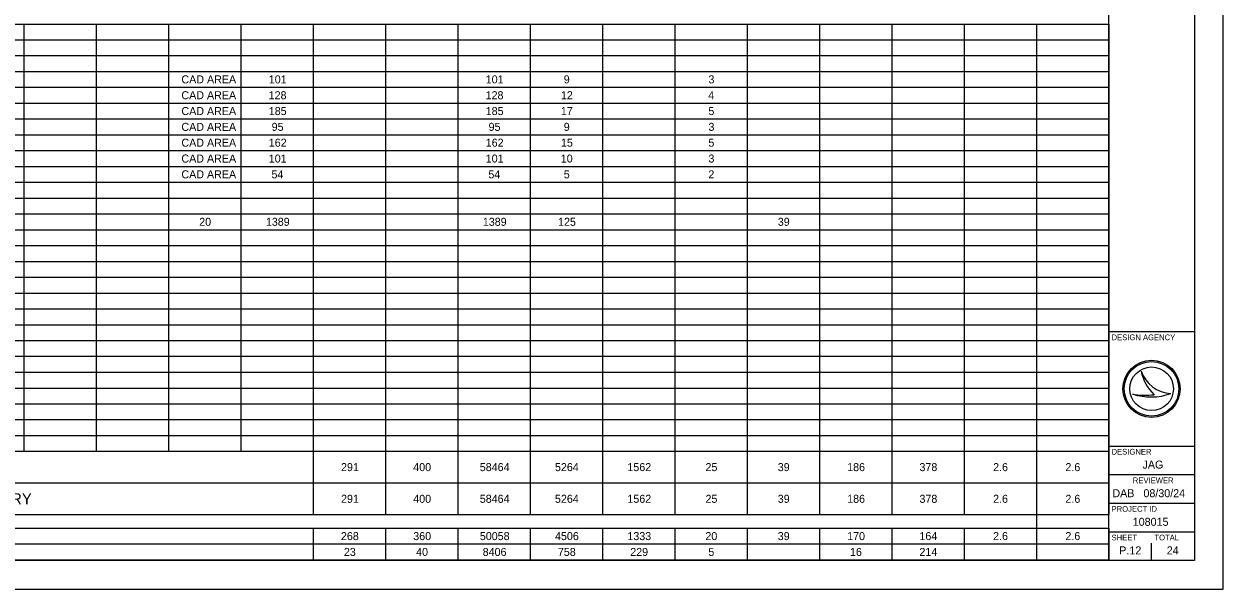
# Model space of a CAD drawing. Extents: x 0 to 34, y 0 to 22.
# Drawn here: x 13.03 to 34, y 0 to 9.88 of the extents above; entities that cross this region are included whole.
import ezdxf

# ---------------------------------------------------------------- set-up
doc = ezdxf.new("R2010")
doc.units = 0
for name, color, linetype in [('SH_Border', 7, 'Continuous'), ('SH_Cut_Line', 7, 'Continuous'), ('SH_Data', 7, 'Continuous'), ('SH_Text', 7, 'Continuous')]:
    doc.layers.add(name, color=color, linetype=linetype)

msp = doc.modelspace()

# ---------------------------------------------------------------- linework, layer by layer
at = {"layer": 'SH_Border'}
for p, q in [((32, 0.5), (32, 21.5)), ((32, 4.5), (33.5, 4.5)), ((32, 2.5), (33.5, 2.5)), ((32, 2), (33.5, 2)), ((32, 1.5), (33.5, 1.5)), ((32, 1), (33.5, 1))]:
    msp.add_line(p, q, dxfattribs=at)
msp.add_lwpolyline([(1.5, 21.5), (33.5, 21.5), (33.5, 0.5), (1.5, 0.5)], close=True, dxfattribs=at)
at = {"layer": 'SH_Cut_Line'}
msp.add_lwpolyline([(0, 0), (34, 0), (34, 22), (0, 22)], close=True, dxfattribs=at)
at = {"layer": 'SH_Data'}
for p, q in [((32.567, 3.81), (32.567, 3.81)), ((32.417, 3.41), (32.417, 3.41)), ((32.75, 3.5), (32.75, 3.5)), ((33.087, 3.419), (33.087, 3.419)), ((32.375, 0.675), (32.375, 0.675)), ((32.75, 0.5), (32.75, 0.8))]:
    msp.add_line(p, q, dxfattribs=at)
for radius in [0.5, 0.477, 0.477, 0.382]:
    msp.add_circle((32.75, 3.5), radius, dxfattribs=at)
for centre, radius, start, end in [((33.116, 3.998), 0.58, 198.9257, 198.9319), ((33.347, 3.97), 0.796, 191.6379, 191.6421), ((33.116, 3.998), 0.58, 198.9319, 267.1657), ((33.347, 3.97), 0.796, 191.6421, 226.0947), ((32.739, 4.37), 1.013, 251.4576, 290.0832), ((32.648, 4.654), 1.266, 259.4964, 259.4995), ((32.739, 4.37), 1.013, 251.4527, 251.4576), ((32.648, 4.654), 1.266, 259.4995, 276.6672)]:
    msp.add_arc(centre, radius, start, end, dxfattribs=at)
at = {"layer": 'SH_Text'}
for p, q in [((8.427, 9.878), (13.026, 9.878)), ((13.026, 9.878), (15.556, 9.878)), ((13.026, 9.878), (13.026, 9.325)), ((14.291, 9.878), (14.291, 9.325)), ((15.556, 9.878), (23.145, 9.878)), ((15.556, 9.878), (15.556, 9.325)), ((16.821, 9.878), (16.821, 9.325)), ((18.086, 9.878), (18.086, 9.325)), ((19.351, 9.878), (19.351, 9.325)), ((20.616, 9.878), (20.616, 9.325)), ((21.88, 9.878), (21.88, 9.325)), ((23.145, 9.878), (24.41, 9.878)), ((23.145, 9.878), (23.145, 9.325)), ((24.41, 9.878), (25.675, 9.878)), ((24.41, 9.878), (24.41, 9.325)), ((25.675, 9.878), (26.94, 9.878)), ((25.675, 9.878), (25.675, 9.325)), ((26.94, 9.878), (28.205, 9.878)), ((26.94, 9.878), (26.94, 9.325)), ((28.205, 9.878), (29.47, 9.878)), ((28.205, 9.878), (28.205, 9.325)), ((29.47, 9.878), (30.735, 9.878)), ((29.47, 9.878), (29.47, 9.325)), ((30.735, 9.878), (32, 9.878)), ((30.735, 9.878), (30.735, 9.325)), ((32, 9.878), (32, 9.325)), ((8.427, 9.602), (13.026, 9.602)), ((13.026, 9.602), (15.556, 9.602)), ((15.556, 9.602), (23.145, 9.602)), ((23.145, 9.602), (24.41, 9.602)), ((24.41, 9.602), (25.675, 9.602)), ((25.675, 9.602), (26.94, 9.602)), ((26.94, 9.602), (28.205, 9.602)), ((28.205, 9.602), (29.47, 9.602)), ((29.47, 9.602), (30.735, 9.602)), ((30.735, 9.602), (32, 9.602)), ((8.427, 9.325), (13.026, 9.325)), ((13.026, 9.325), (15.556, 9.325)), ((13.026, 9.325), (13.026, 8.495)), ((14.291, 9.325), (14.291, 8.495)), ((15.556, 9.325), (23.145, 9.325)), ((15.556, 9.325), (15.556, 8.495)), ((16.821, 9.325), (16.821, 8.495)), ((18.086, 9.325), (18.086, 8.495)), ((19.351, 9.325), (19.351, 8.495)), ((20.616, 9.325), (20.616, 8.495)), ((21.88, 9.325), (21.88, 8.495)), ((23.145, 9.325), (24.41, 9.325)), ((23.145, 9.325), (23.145, 8.495)), ((24.41, 9.325), (25.675, 9.325)), ((24.41, 9.325), (24.41, 8.495)), ((25.675, 9.325), (26.94, 9.325)), ((25.675, 9.325), (25.675, 8.495)), ((26.94, 9.325), (28.205, 9.325)), ((26.94, 9.325), (26.94, 8.495)), ((28.205, 9.325), (29.47, 9.325)), ((28.205, 9.325), (28.205, 8.495)), ((29.47, 9.325), (30.735, 9.325)), ((29.47, 9.325), (29.47, 8.495)), ((30.735, 9.325), (32, 9.325)), ((30.735, 9.325), (30.735, 8.495)), ((32, 9.325), (32, 8.495)), ((8.427, 9.048), (13.026, 9.048)), ((13.026, 9.048), (15.556, 9.048)), ((15.556, 9.048), (23.145, 9.048)), ((23.145, 9.048), (24.41, 9.048)), ((24.41, 9.048), (25.675, 9.048)), ((25.675, 9.048), (26.94, 9.048)), ((26.94, 9.048), (28.205, 9.048)), ((28.205, 9.048), (29.47, 9.048)), ((29.47, 9.048), (30.735, 9.048)), ((30.735, 9.048), (32, 9.048)), ((8.427, 8.772), (13.026, 8.772)), ((13.026, 8.772), (15.556, 8.772)), ((15.556, 8.772), (23.145, 8.772)), ((23.145, 8.772), (24.41, 8.772)), ((24.41, 8.772), (25.675, 8.772)), ((25.675, 8.772), (26.94, 8.772)), ((26.94, 8.772), (28.205, 8.772)), ((28.205, 8.772), (29.47, 8.772)), ((29.47, 8.772), (30.735, 8.772)), ((30.735, 8.772), (32, 8.772)), ((8.427, 8.495), (13.026, 8.495)), ((13.026, 8.495), (15.556, 8.495)), ((13.026, 8.495), (13.026, 7.941)), ((14.291, 8.495), (14.291, 7.941)), ((15.556, 8.495), (23.145, 8.495)), ((15.556, 8.495), (15.556, 7.941)), ((16.821, 8.495), (16.821, 7.941)), ((18.086, 8.495), (18.086, 7.941)), ((19.351, 8.495), (19.351, 7.941)), ((20.616, 8.495), (20.616, 7.941)), ((21.88, 8.495), (21.88, 7.941)), ((23.145, 8.495), (24.41, 8.495)), ((23.145, 8.495), (23.145, 7.941)), ((24.41, 8.495), (25.675, 8.495)), ((24.41, 8.495), (24.41, 7.941)), ((25.675, 8.495), (26.94, 8.495)), ((25.675, 8.495), (25.675, 7.941)), ((26.94, 8.495), (28.205, 8.495)), ((26.94, 8.495), (26.94, 7.941)), ((28.205, 8.495), (29.47, 8.495)), ((28.205, 8.495), (28.205, 7.941)), ((29.47, 8.495), (30.735, 8.495)), ((29.47, 8.495), (29.47, 7.941)), ((30.735, 8.495), (32, 8.495)), ((30.735, 8.495), (30.735, 7.941)), ((32, 8.495), (32, 7.941)), ((8.427, 8.218), (13.026, 8.218)), ((13.026, 8.218), (15.556, 8.218)), ((15.556, 8.218), (23.145, 8.218)), ((23.145, 8.218), (24.41, 8.218)), ((24.41, 8.218), (25.675, 8.218)), ((25.675, 8.218), (26.94, 8.218)), ((26.94, 8.218), (28.205, 8.218)), ((28.205, 8.218), (29.47, 8.218)), ((29.47, 8.218), (30.735, 8.218)), ((30.735, 8.218), (32, 8.218)), ((8.427, 7.941), (13.026, 7.941)), ((13.026, 7.941), (15.556, 7.941)), ((13.026, 7.941), (13.026, 7.111)), ((14.291, 7.941), (14.291, 7.111)), ((15.556, 7.941), (23.145, 7.941)), ((15.556, 7.941), (15.556, 7.111)), ((16.821, 7.941), (16.821, 7.111)), ((18.086, 7.941), (18.086, 7.111)), ((19.351, 7.941), (19.351, 7.111)), ((20.616, 7.941), (20.616, 7.111)), ((21.88, 7.941), (21.88, 7.111)), ((23.145, 7.941), (24.41, 7.941)), ((23.145, 7.941), (23.145, 7.111)), ((24.41, 7.941), (25.675, 7.941)), ((24.41, 7.941), (24.41, 7.111)), ((25.675, 7.941), (26.94, 7.941)), ((25.675, 7.941), (25.675, 7.111)), ((26.94, 7.941), (28.205, 7.941)), ((26.94, 7.941), (26.94, 7.111)), ((28.205, 7.941), (29.47, 7.941)), ((28.205, 7.941), (28.205, 7.111)), ((29.47, 7.941), (30.735, 7.941)), ((29.47, 7.941), (29.47, 7.111)), ((30.735, 7.941), (32, 7.941)), ((30.735, 7.941), (30.735, 7.111)), ((32, 7.941), (32, 7.111)), ((8.427, 7.665), (13.026, 7.665)), ((13.026, 7.665), (15.556, 7.665)), ((15.556, 7.665), (23.145, 7.665)), ((23.145, 7.665), (24.41, 7.665)), ((24.41, 7.665), (25.675, 7.665)), ((25.675, 7.665), (26.94, 7.665)), ((26.94, 7.665), (28.205, 7.665)), ((28.205, 7.665), (29.47, 7.665)), ((29.47, 7.665), (30.735, 7.665)), ((30.735, 7.665), (32, 7.665)), ((8.427, 7.388), (13.026, 7.388)), ((13.026, 7.388), (15.556, 7.388)), ((15.556, 7.388), (23.145, 7.388)), ((23.145, 7.388), (24.41, 7.388)), ((24.41, 7.388), (25.675, 7.388)), ((25.675, 7.388), (26.94, 7.388)), ((26.94, 7.388), (28.205, 7.388)), ((28.205, 7.388), (29.47, 7.388)), ((29.47, 7.388), (30.735, 7.388)), ((30.735, 7.388), (32, 7.388)), ((8.427, 7.111), (13.026, 7.111)), ((13.026, 7.111), (15.556, 7.111)), ((13.026, 7.111), (13.026, 6.558)), ((14.291, 7.111), (14.291, 6.558)), ((15.556, 7.111), (23.145, 7.111)), ((15.556, 7.111), (15.556, 6.558)), ((16.821, 7.111), (16.821, 6.558)), ((18.086, 7.111), (18.086, 6.558)), ((19.351, 7.111), (19.351, 6.558)), ((20.616, 7.111), (20.616, 6.558)), ((21.88, 7.111), (21.88, 6.558)), ((23.145, 7.111), (24.41, 7.111)), ((23.145, 7.111), (23.145, 6.558)), ((24.41, 7.111), (25.675, 7.111)), ((24.41, 7.111), (24.41, 6.558)), ((25.675, 7.111), (26.94, 7.111)), ((25.675, 7.111), (25.675, 6.558)), ((26.94, 7.111), (28.205, 7.111)), ((26.94, 7.111), (26.94, 6.558)), ((28.205, 7.111), (29.47, 7.111)), ((28.205, 7.111), (28.205, 6.558)), ((29.47, 7.111), (30.735, 7.111)), ((29.47, 7.111), (29.47, 6.558)), ((30.735, 7.111), (32, 7.111)), ((30.735, 7.111), (30.735, 6.558)), ((32, 7.111), (32, 6.558)), ((8.427, 6.835), (13.026, 6.835)), ((13.026, 6.835), (15.556, 6.835)), ((15.556, 6.835), (23.145, 6.835)), ((23.145, 6.835), (24.41, 6.835)), ((24.41, 6.835), (25.675, 6.835)), ((25.675, 6.835), (26.94, 6.835)), ((26.94, 6.835), (28.205, 6.835)), ((28.205, 6.835), (29.47, 6.835)), ((29.47, 6.835), (30.735, 6.835)), ((30.735, 6.835), (32, 6.835)), ((8.427, 6.558), (13.026, 6.558)), ((13.026, 6.558), (15.556, 6.558)), ((13.026, 6.558), (13.026, 2.407)), ((14.291, 6.558), (14.291, 2.407)), ((15.556, 6.558), (23.145, 6.558)), ((15.556, 6.558), (15.556, 2.407)), ((16.821, 6.558), (16.821, 2.407)), ((18.086, 6.558), (18.086, 1.3)), ((19.351, 6.558), (19.351, 1.3)), ((20.616, 6.558), (20.616, 1.3)), ((21.88, 6.558), (21.88, 1.3)), ((23.145, 6.558), (24.41, 6.558)), ((23.145, 6.558), (23.145, 1.3)), ((24.41, 6.558), (25.675, 6.558)), ((24.41, 6.558), (24.41, 1.3)), ((25.675, 6.558), (26.94, 6.558)), ((25.675, 6.558), (25.675, 1.3)), ((26.94, 6.558), (28.205, 6.558)), ((26.94, 6.558), (26.94, 1.3)), ((28.205, 6.558), (29.47, 6.558)), ((28.205, 6.558), (28.205, 1.3)), ((29.47, 6.558), (30.735, 6.558)), ((29.47, 6.558), (29.47, 1.3)), ((30.735, 6.558), (32, 6.558)), ((30.735, 6.558), (30.735, 0.51)), ((32, 6.558), (32, 1.3)), ((8.427, 6.281), (13.026, 6.281)), ((13.026, 6.281), (15.556, 6.281)), ((15.556, 6.281), (23.145, 6.281)), ((23.145, 6.281), (24.41, 6.281)), ((24.41, 6.281), (25.675, 6.281)), ((25.675, 6.281), (26.94, 6.281)), ((26.94, 6.281), (28.205, 6.281)), ((28.205, 6.281), (29.47, 6.281)), ((29.47, 6.281), (30.735, 6.281)), ((30.735, 6.281), (32, 6.281)), ((8.427, 6.004), (13.026, 6.004)), ((13.026, 6.004), (15.556, 6.004)), ((15.556, 6.004), (23.145, 6.004)), ((23.145, 6.004), (24.41, 6.004)), ((24.41, 6.004), (25.675, 6.004)), ((25.675, 6.004), (26.94, 6.004)), ((26.94, 6.004), (28.205, 6.004)), ((28.205, 6.004), (29.47, 6.004)), ((29.47, 6.004), (30.735, 6.004)), ((30.735, 6.004), (32, 6.004)), ((8.427, 5.728), (13.026, 5.728)), ((13.026, 5.728), (15.556, 5.728)), ((15.556, 5.728), (23.145, 5.728)), ((23.145, 5.728), (24.41, 5.728)), ((24.41, 5.728), (25.675, 5.728)), ((25.675, 5.728), (26.94, 5.728)), ((26.94, 5.728), (28.205, 5.728)), ((28.205, 5.728), (29.47, 5.728)), ((29.47, 5.728), (30.735, 5.728)), ((30.735, 5.728), (32, 5.728)), ((8.427, 5.451), (13.026, 5.451)), ((13.026, 5.451), (15.556, 5.451)), ((15.556, 5.451), (23.145, 5.451)), ((23.145, 5.451), (24.41, 5.451)), ((24.41, 5.451), (25.675, 5.451)), ((25.675, 5.451), (26.94, 5.451)), ((26.94, 5.451), (28.205, 5.451)), ((28.205, 5.451), (29.47, 5.451)), ((29.47, 5.451), (30.735, 5.451)), ((30.735, 5.451), (32, 5.451)), ((8.427, 5.174), (13.026, 5.174)), ((13.026, 5.174), (15.556, 5.174)), ((15.556, 5.174), (23.145, 5.174)), ((23.145, 5.174), (24.41, 5.174)), ((24.41, 5.174), (25.675, 5.174)), ((25.675, 5.174), (26.94, 5.174)), ((26.94, 5.174), (28.205, 5.174)), ((28.205, 5.174), (29.47, 5.174)), ((29.47, 5.174), (30.735, 5.174)), ((30.735, 5.174), (32, 5.174)), ((8.427, 4.898), (13.026, 4.898)), ((13.026, 4.898), (15.556, 4.898)), ((15.556, 4.898), (23.145, 4.898)), ((23.145, 4.898), (24.41, 4.898)), ((24.41, 4.898), (25.675, 4.898)), ((25.675, 4.898), (26.94, 4.898)), ((26.94, 4.898), (28.205, 4.898)), ((28.205, 4.898), (29.47, 4.898)), ((29.47, 4.898), (30.735, 4.898)), ((30.735, 4.898), (32, 4.898)), ((8.427, 4.621), (13.026, 4.621)), ((13.026, 4.621), (15.556, 4.621)), ((15.556, 4.621), (23.145, 4.621)), ((23.145, 4.621), (24.41, 4.621)), ((24.41, 4.621), (25.675, 4.621)), ((25.675, 4.621), (26.94, 4.621)), ((26.94, 4.621), (28.205, 4.621)), ((28.205, 4.621), (29.47, 4.621)), ((29.47, 4.621), (30.735, 4.621)), ((30.735, 4.621), (32, 4.621)), ((8.427, 4.344), (13.026, 4.344)), ((13.026, 4.344), (15.556, 4.344)), ((15.556, 4.344), (23.145, 4.344)), ((23.145, 4.344), (24.41, 4.344)), ((24.41, 4.344), (25.675, 4.344)), ((25.675, 4.344), (26.94, 4.344)), ((26.94, 4.344), (28.205, 4.344)), ((28.205, 4.344), (29.47, 4.344)), ((29.47, 4.344), (30.735, 4.344)), ((30.735, 4.344), (32, 4.344)), ((8.427, 4.068), (13.026, 4.068)), ((13.026, 4.068), (15.556, 4.068)), ((15.556, 4.068), (23.145, 4.068)), ((23.145, 4.068), (24.41, 4.068)), ((24.41, 4.068), (25.675, 4.068)), ((25.675, 4.068), (26.94, 4.068)), ((26.94, 4.068), (28.205, 4.068)), ((28.205, 4.068), (29.47, 4.068)), ((29.47, 4.068), (30.735, 4.068)), ((30.735, 4.068), (32, 4.068)), ((8.427, 3.791), (13.026, 3.791)), ((13.026, 3.791), (15.556, 3.791)), ((15.556, 3.791), (23.145, 3.791)), ((23.145, 3.791), (24.41, 3.791)), ((24.41, 3.791), (25.675, 3.791)), ((25.675, 3.791), (26.94, 3.791)), ((26.94, 3.791), (28.205, 3.791)), ((28.205, 3.791), (29.47, 3.791)), ((29.47, 3.791), (30.735, 3.791)), ((30.735, 3.791), (32, 3.791)), ((8.427, 3.514), (13.026, 3.514)), ((13.026, 3.514), (15.556, 3.514)), ((15.556, 3.514), (23.145, 3.514)), ((23.145, 3.514), (24.41, 3.514)), ((24.41, 3.514), (25.675, 3.514)), ((25.675, 3.514), (26.94, 3.514)), ((26.94, 3.514), (28.205, 3.514)), ((28.205, 3.514), (29.47, 3.514)), ((29.47, 3.514), (30.735, 3.514)), ((30.735, 3.514), (32, 3.514)), ((8.427, 3.237), (13.026, 3.237)), ((13.026, 3.237), (15.556, 3.237)), ((15.556, 3.237), (23.145, 3.237)), ((23.145, 3.237), (24.41, 3.237)), ((24.41, 3.237), (25.675, 3.237)), ((25.675, 3.237), (26.94, 3.237)), ((26.94, 3.237), (28.205, 3.237)), ((28.205, 3.237), (29.47, 3.237)), ((29.47, 3.237), (30.735, 3.237)), ((30.735, 3.237), (32, 3.237)), ((8.427, 2.961), (13.026, 2.961)), ((13.026, 2.961), (15.556, 2.961)), ((15.556, 2.961), (23.145, 2.961)), ((23.145, 2.961), (24.41, 2.961)), ((24.41, 2.961), (25.675, 2.961)), ((25.675, 2.961), (26.94, 2.961)), ((26.94, 2.961), (28.205, 2.961)), ((28.205, 2.961), (29.47, 2.961)), ((29.47, 2.961), (30.735, 2.961)), ((30.735, 2.961), (32, 2.961)), ((8.427, 2.684), (13.026, 2.684)), ((13.026, 2.684), (15.556, 2.684)), ((15.556, 2.684), (23.145, 2.684)), ((23.145, 2.684), (24.41, 2.684)), ((24.41, 2.684), (25.675, 2.684)), ((25.675, 2.684), (26.94, 2.684)), ((26.94, 2.684), (28.205, 2.684)), ((28.205, 2.684), (29.47, 2.684)), ((29.47, 2.684), (30.735, 2.684)), ((30.735, 2.684), (32, 2.684)), ((8.427, 2.407), (13.026, 2.407)), ((13.026, 2.407), (15.556, 2.407)), ((15.556, 2.407), (23.145, 2.407)), ((23.145, 2.407), (24.41, 2.407)), ((24.41, 2.407), (25.675, 2.407)), ((25.675, 2.407), (26.94, 2.407)), ((26.94, 2.407), (28.205, 2.407)), ((28.205, 2.407), (29.47, 2.407)), ((29.47, 2.407), (30.735, 2.407)), ((30.735, 2.407), (32, 2.407)), ((8.427, 1.854), (13.026, 1.854)), ((13.026, 1.854), (15.556, 1.854)), ((15.556, 1.854), (23.145, 1.854)), ((23.145, 1.854), (24.41, 1.854)), ((24.41, 1.854), (25.675, 1.854)), ((25.675, 1.854), (26.94, 1.854)), ((26.94, 1.854), (28.205, 1.854)), ((28.205, 1.854), (29.47, 1.854)), ((29.47, 1.854), (30.735, 1.854)), ((30.735, 1.854), (32, 1.854)), ((8.427, 1.3), (13.026, 1.3)), ((13.026, 1.3), (15.556, 1.3)), ((15.556, 1.3), (23.145, 1.3)), ((23.145, 1.3), (24.41, 1.3)), ((24.41, 1.3), (25.675, 1.3)), ((25.675, 1.3), (26.94, 1.3)), ((26.94, 1.3), (28.205, 1.3)), ((28.205, 1.3), (29.47, 1.3)), ((29.47, 1.3), (30.735, 1.3)), ((30.735, 1.3), (32, 1.3)), ((8.427, 1.063), (13.026, 1.063)), ((13.026, 1.063), (15.556, 1.063)), ((15.556, 1.063), (23.145, 1.063)), ((18.086, 1.063), (18.086, 0.51)), ((19.351, 1.063), (19.351, 0.51)), ((20.616, 1.063), (20.616, 0.51)), ((21.88, 1.063), (21.88, 0.51)), ((23.145, 1.063), (24.41, 1.063)), ((23.145, 1.063), (23.145, 0.51)), ((24.41, 1.063), (25.675, 1.063)), ((24.41, 1.063), (24.41, 0.51)), ((25.675, 1.063), (26.94, 1.063)), ((25.675, 1.063), (25.675, 0.51)), ((26.94, 1.063), (28.205, 1.063)), ((26.94, 1.063), (26.94, 0.51)), ((28.205, 1.063), (29.47, 1.063)), ((28.205, 1.063), (28.205, 0.51)), ((29.47, 1.063), (30.735, 1.063)), ((29.47, 1.063), (29.47, 0.51)), ((30.735, 1.063), (32, 1.063)), ((32, 1.063), (32, 0.51)), ((8.427, 0.787), (13.026, 0.787)), ((13.026, 0.787), (15.556, 0.787)), ((15.556, 0.787), (23.145, 0.787)), ((23.145, 0.787), (24.41, 0.787)), ((24.41, 0.787), (25.675, 0.787)), ((25.675, 0.787), (26.94, 0.787)), ((26.94, 0.787), (28.205, 0.787)), ((28.205, 0.787), (29.47, 0.787)), ((29.47, 0.787), (30.735, 0.787)), ((30.735, 0.787), (32, 0.787)), ((8.427, 0.51), (13.026, 0.51)), ((13.026, 0.51), (15.556, 0.51)), ((15.556, 0.51), (23.145, 0.51)), ((23.145, 0.51), (24.41, 0.51)), ((24.41, 0.51), (25.675, 0.51)), ((25.675, 0.51), (26.94, 0.51)), ((26.94, 0.51), (28.205, 0.51)), ((28.205, 0.51), (29.47, 0.51)), ((29.47, 0.51), (30.735, 0.51)), ((30.735, 0.51), (32, 0.51))]:
    msp.add_line(p, q, dxfattribs=at)

# ---------------------------------------------------------------- texts
at = {"layer": 'SH_Data'}
for s, height, p in [('DESIGN AGENCY', 0.1, (32.05, 4.35)), ('DESIGNER', 0.1, (32.05, 2.35)), ('JAG', 0.14, (32.592, 2.105)), ('REVIEWER', 0.1, (32.422, 1.85)), ('DAB', 0.14, (32.065, 1.605)), ('08/30/24', 0.14, (32.608, 1.605)), ('PROJECT ID', 0.1, (32.05, 1.35)), ('108015', 0.14, (32.421, 1.105)), ('SHEET', 0.1, (32.05, 0.85)), ('TOTAL', 0.1, (32.8, 0.85)), ('P.12', 0.14, (32.185, 0.605)), ('24', 0.14, (33.016, 0.605))]:
    msp.add_text(s, height=height, dxfattribs=at).set_placement(p)
at = {"layer": 'SH_Text'}
for s, height, p in [('CAD AREA', 0.14, (15.78, 8.84)), ('101', 0.14, (17.308, 8.84)), ('101', 0.14, (21.103, 8.84)), ('9', 0.14, (22.468, 8.84)), ('3', 0.14, (24.999, 8.84)), ('CAD AREA', 0.14, (15.78, 8.563)), ('128', 0.14, (17.306, 8.563)), ('128', 0.14, (21.101, 8.563)), ('12', 0.14, (22.418, 8.563)), ('4', 0.14, (24.995, 8.563)), ('CAD AREA', 0.14, (15.78, 8.286)), ('185', 0.14, (17.308, 8.286)), ('185', 0.14, (21.103, 8.286)), ('17', 0.14, (22.417, 8.286)), ('5', 0.14, (24.998, 8.286)), ('CAD AREA', 0.14, (15.78, 8.01)), ('95', 0.14, (17.358, 8.01)), ('95', 0.14, (21.153, 8.01)), ('9', 0.14, (22.468, 8.01)), ('3', 0.14, (24.999, 8.01)), ('CAD AREA', 0.14, (15.78, 7.733)), ('162', 0.14, (17.308, 7.733)), ('162', 0.14, (21.103, 7.733)), ('15', 0.14, (22.418, 7.733)), ('5', 0.14, (24.998, 7.733)), ('CAD AREA', 0.14, (15.78, 7.456)), ('101', 0.14, (17.308, 7.456)), ('101', 0.14, (21.103, 7.456)), ('10', 0.14, (22.416, 7.456)), ('3', 0.14, (24.999, 7.456)), ('CAD AREA', 0.14, (15.78, 7.18)), ('54', 0.14, (17.355, 7.18)), ('54', 0.14, (21.15, 7.18)), ('5', 0.14, (22.468, 7.18)), ('2', 0.14, (24.998, 7.18)), ('20', 0.14, (16.091, 6.35)), ('1389', 0.14, (17.257, 6.35)), ('1389', 0.14, (21.052, 6.35)), ('125', 0.14, (22.368, 6.35)), ('39', 0.14, (26.212, 6.35)), ('291', 0.14, (18.572, 2.061)), ('400', 0.14, (19.835, 2.061)), ('58464', 0.14, (20.999, 2.061)), ('5264', 0.14, (22.314, 2.061)), ('1562', 0.14, (23.581, 2.061)), ('25', 0.14, (24.947, 2.061)), ('39', 0.14, (26.211, 2.061)), ('186', 0.14, (27.425, 2.061)), ('378', 0.14, (28.69, 2.061)), ('2.6', 0.14, (29.978, 2.061)), ('2.6', 0.14, (31.243, 2.061)), ('TOTALS CARRIED TO GENERAL SUMMARY', 0.196, (7.717, 1.479)), ('291', 0.14, (18.572, 1.507)), ('400', 0.14, (19.835, 1.507)), ('58464', 0.14, (20.999, 1.507)), ('5264', 0.14, (22.314, 1.507)), ('1562', 0.14, (23.581, 1.507)), ('25', 0.14, (24.947, 1.507)), ('39', 0.14, (26.211, 1.507)), ('186', 0.14, (27.425, 1.507)), ('378', 0.14, (28.69, 1.507)), ('2.6', 0.14, (29.978, 1.507)), ('2.6', 0.14, (31.243, 1.507)), ('268', 0.14, (18.57, 0.855)), ('360', 0.14, (19.835, 0.855)), ('50058', 0.14, (21, 0.855)), ('4506', 0.14, (22.315, 0.855)), ('1333', 0.14, (23.581, 0.855)), ('20', 0.14, (24.945, 0.855)), ('39', 0.14, (26.211, 0.855)), ('170', 0.14, (27.425, 0.855)), ('164', 0.14, (28.689, 0.855)), ('2.6', 0.14, (29.978, 0.855)), ('2.6', 0.14, (31.243, 0.855)), ('23', 0.14, (18.622, 0.578)), ('40', 0.14, (19.885, 0.578)), ('8406', 0.14, (21.05, 0.578)), ('758', 0.14, (22.365, 0.578)), ('229', 0.14, (23.631, 0.578)), ('5', 0.14, (24.997, 0.578)), ('16', 0.14, (27.475, 0.578)), ('214', 0.14, (28.689, 0.578))]:
    msp.add_text(s, height=height, dxfattribs=at).set_placement(p)

doc.saveas('drawing.dxf')
